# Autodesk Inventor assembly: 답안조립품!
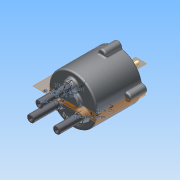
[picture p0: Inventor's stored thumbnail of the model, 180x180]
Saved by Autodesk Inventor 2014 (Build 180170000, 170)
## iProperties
Created: 2015-09
Part Number: 답안조립품!
Document SubType Name: Assembly
Designer: study
Mass: 501 g
Surface Area: 1801.32 cm^2
Volume: 438.544 cm^3
Author: study
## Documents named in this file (14)
- C:\Users\study\Desktop\350916V1012\답안조립품!.iam
- C:\Users\study\Desktop\350916V1012\몸체.ipt
- C:\Users\study\Desktop\350916V1012\메인 축.ipt
- C:\Users\study\Desktop\350916V1012\판캠.ipt
- C:\Users\study\Desktop\350916V1012\멈춤링 10 x 1.ipt
- C:\Users\study\Desktop\350916V1012\멈춤링 22 x 1.2.ipt
- C:\Users\study\Desktop\350916V1012\슬라이드 축.ipt
- C:\Users\study\Desktop\350916V1012\베어링 NA 4900.ipt
- C:\Users\study\Desktop\350916V1012\오일실.ipt
- C:\Users\study\Desktop\350916V1012\커버.ipt
- C:\Users\study\Desktop\350916V1012\M5x0.8x20.ipt
- C:\Users\study\Desktop\350916V1012\가변스프링.ipt
- C:\Users\study\Desktop\350916V1012\가변스프링2.ipt
- C:\Users\study\Desktop\350916V1012\가변스프링3.ipt
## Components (7 placed, 4 different names)
1. 가변스프링:1
2. 가변스프링2:1
3. 가변스프링3:1
4. M5x0.8x20:1
5. M5x0.8x20:2
6. M5x0.8x20:3
7. M5x0.8x20:4
